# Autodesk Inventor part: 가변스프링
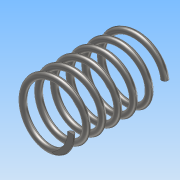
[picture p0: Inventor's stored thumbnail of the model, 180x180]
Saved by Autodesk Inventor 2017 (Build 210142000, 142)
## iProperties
Part Number: 가변스프링
Material: 스테인레스 스틸
Document SubType Name: Modeling
Designer: user
Density: 8 g/cm^3
Appearance: 반연마
Mass: 8.46793 g
Surface Area: 21.3602 cm^2
Volume: 1.05849 cm^3
Author: user
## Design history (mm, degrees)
sketch "스케치1"
  geometry: L1 (-9, 0)-(9, 0); L2 (0, 0)-(0, 30.5); L3 (0, 30.5)-(17.575, 30.5); C1 r 1 at (9, 0); 1 further point
  constraints: 6 end point, 2 coincident, 2 horizontal, 1 centre point, 1 midpoint, 1 vertical
  dimensions: "d0" = 18 distance of L1.start L1.end; "d1" = 30.5 distance of L2.start L2.end (derived); "d2" = 2 diameter of C1
feature "코일1" sketch "스케치1" pitch "d3" = 10; turns "d5" = 6; dims "d4" = 30.5 (= d1), "d6" = 0, angle "d7" = 90 deg, angle "d8" = 90 deg, "d9" = 0, "d10" = 0
sketch "스케치2"
  geometry: L1 (-12.5, 40)-(12.5, 40); L2 (12.5, 40)-(12.5, 0); L3 (12.5, 0)-(-12.5, 0); L4 (-12.5, 0)-(-12.5, 40); 2 further points
  constraints: 8 end point, 2 parallel, 1 coincident, 1 horizontal, 1 midpoint, 1 perpendicular
  dimensions: "d11" = 40 distance of L3.end L1.start (derived); "d12" = 25 distance of L1.start L1.end
extrude "돌출1" sketch "스케치2" stored distance "d13" = 100; taper "d14" = 0 deg
node "솔리드1"
